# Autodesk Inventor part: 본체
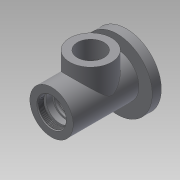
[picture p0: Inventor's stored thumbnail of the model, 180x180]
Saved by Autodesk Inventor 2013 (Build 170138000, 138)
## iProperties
Created: 2016-08
Part Number: 본체
Material: Generic
Document SubType Name: Modeling
Designer: Administrator
Density: 1 g/cm^3
Author: Administrator
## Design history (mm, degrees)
sketch "스케치2"
  geometry: L1 (0, 31)-(0, 0); L2 (9, 0)-(9, 24); L3 (9, 24)-(12, 24); L4 (12, 24)-(12, 20); L5 (12, 20)-(21, 20); L6 (21, 20)-(21, 17.5); L7 (21, 17.5)-(24.25, 17.5); L8 (24.25, 17.5)-(24.25, 18.5); L9 (24.25, 18.5)-(26, 18.5); L10 (26, 18.5)-(26, 17.5); L11 (26, 17.5)-(37, 17.5); L12 (37, 17.5)-(37, 26); L13 (37, 26)-(75, 26); L14 (75, 26)-(75, 17.5); L15 (86, 16.5)-(86, 10); L16 (86, 10)-(88.7, 10); L17 (110, 21)-(110, 31); L18 (110, 31)-(107, 31); L19 (107, 31)-(107, 50); L20 (107, 50)-(94, 50); L21 (94, 50)-(94, 31); L22 (94, 31)-(0, 31); L23 (0, 0)-(115, 0); L24 (88.7, 10)-(88.7, 12.5); L25 (88.7, 12.5)-(96, 12.5); L26 (96, 12.5)-(96, 16); L27 (96, 16)-(110, 21); L28 (75, 17.5)-(81, 17.5); L29 (81, 17.5)-(81, 16.5); L30 (81, 16.5)-(86, 16.5); L31 (56, 26)-(56, 0)
  constraints: 62 end point, 16 parallel, 9 perpendicular, 2 point on line, 1 midpoint, 1 vertical
  dimensions: "d0" = 62 diameter of L22 L23; "d3" = 40 diameter of L5 L23; "d4" = 48 diameter of L3 L23; "d5" = 3 distance between parallel lines of L4 L2; "d6" = 12 distance between parallel lines of L1 L4; "d7" = 21 distance between parallel lines of L1 L6; "d9" = 26 distance between parallel lines of L1 L10; "d12" = 37 diameter of L9 L23; "d13" = 35 diameter of L7 L23; "d14" = 1.75 distance between parallel lines of L10 L8; "d15" = 35 diameter of L11 L23; "d18" = 52 diameter of L13 L23; "d20" = 60 distance between parallel lines of L15 L10; "d23" = 14 distance from line of L17 L25.end; "d24" = 2.7 distance of L15.end L16.end; "d25" = 7.3 distance of L24.end L25.end; "d27" = 20 diameter of L16 L23; "d28" = 25 diameter of L25 L23; "d29" = 32 diameter of L26.end L23; "d30" = 42 diameter of L17.start L23; "d31" = 3 distance between parallel lines of L17 L19; "d32" = 13 distance between parallel lines of L19 L21; "d33" = 100 diameter of L20 L23; "d34" = 62 diameter of L18 L23; "d35" = 115 distance of L1.end L23.end; "d36" = 33 diameter of L30 L23; "d37" = 5 distance of L29.end L15.start; "d38" = 35 diameter of L28 L23; "d76" = 56 distance between parallel lines of L1 L31; "d77" = 19 distance between parallel lines of L12 L31; "d78" = 38 distance between parallel lines of L12 L14
revolve "회전1" sketch "스케치2" stored, may be unused: angle "d41" = 90 deg
sketch "스케치3"
  geometry: C1 r 31 at (0, 0) reference; C2 r 21 at (0, 0)
  constraints: 1 centre point, 1 coincident
  dimensions: "d42" = 42 diameter of C2
hole "구멍1" sketch "스케치3" at (0, 0) diameter "d44" = 40.376; stored, may be unused: countersink angle "d48" = 90 deg, drill point angle "d50" = 118 deg; dims "d45" = 6, "d46" = 4, "d47" = 2, "d49" = 9
fillet "모깎기1" dims "d51" = 3
chamfer "모따기1" distance "d52" = 1; stored, may be unused: second distance "d53" = 2, angle "d54" = 30 deg
fillet "모깎기2" dims "d55" = 3
chamfer "모따기2" distance "d56" = 0.7; stored, may be unused: second distance "d57" = 2, angle "d58" = 30 deg
fillet "모깎기3" dims "d59" = 0.3
fillet "모깎기4" dims "d60" = 0.3
chamfer "모따기3" distance "d61" = 1; stored, may be unused: second distance "d62" = 2, angle "d63" = 30 deg
chamfer "모따기4" distance "d64" = 1; stored, may be unused: second distance "d65" = 2, angle "d66" = 30 deg
node "작업 평면1"
sketch "스케치4"
  geometry: L1 (31, 0)-(-31, 0) reference; C1 r 30 at (0, 56); 2 further points
  constraints: 1 centre point, 1 midpoint, 1 vertical alignment
  dimensions: "d68" = 56 distance from line of L1 C1.centre; "d69" = 60 diameter of C1
extrude "돌출1" join sketch "스케치4" stored distance "d70" = 10; taper "d71" = 0 deg
sketch "스케치5"
  geometry: C1 r 30 at (0, 0) reference; C2 r 19 at (0, 0); 1 further point
  constraints: 1 centre point, 1 coincident
  dimensions: "d72" = 38 diameter of C2
extrude "돌출2" cut sketch "스케치5" stored distance "d74" = 10; taper "d75" = 0 deg
node "솔리드1"
other parameters: "d67" = 49
